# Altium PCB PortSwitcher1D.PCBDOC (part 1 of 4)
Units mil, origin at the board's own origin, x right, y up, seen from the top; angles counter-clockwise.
Board outline 6005.03 x 6005.03 mil, 4 copper layers (Top Layer, InternalPlane1, InternalPlane2, Bottom Layer); 153 components, 325 nets, 1175 pads, 173 vias.
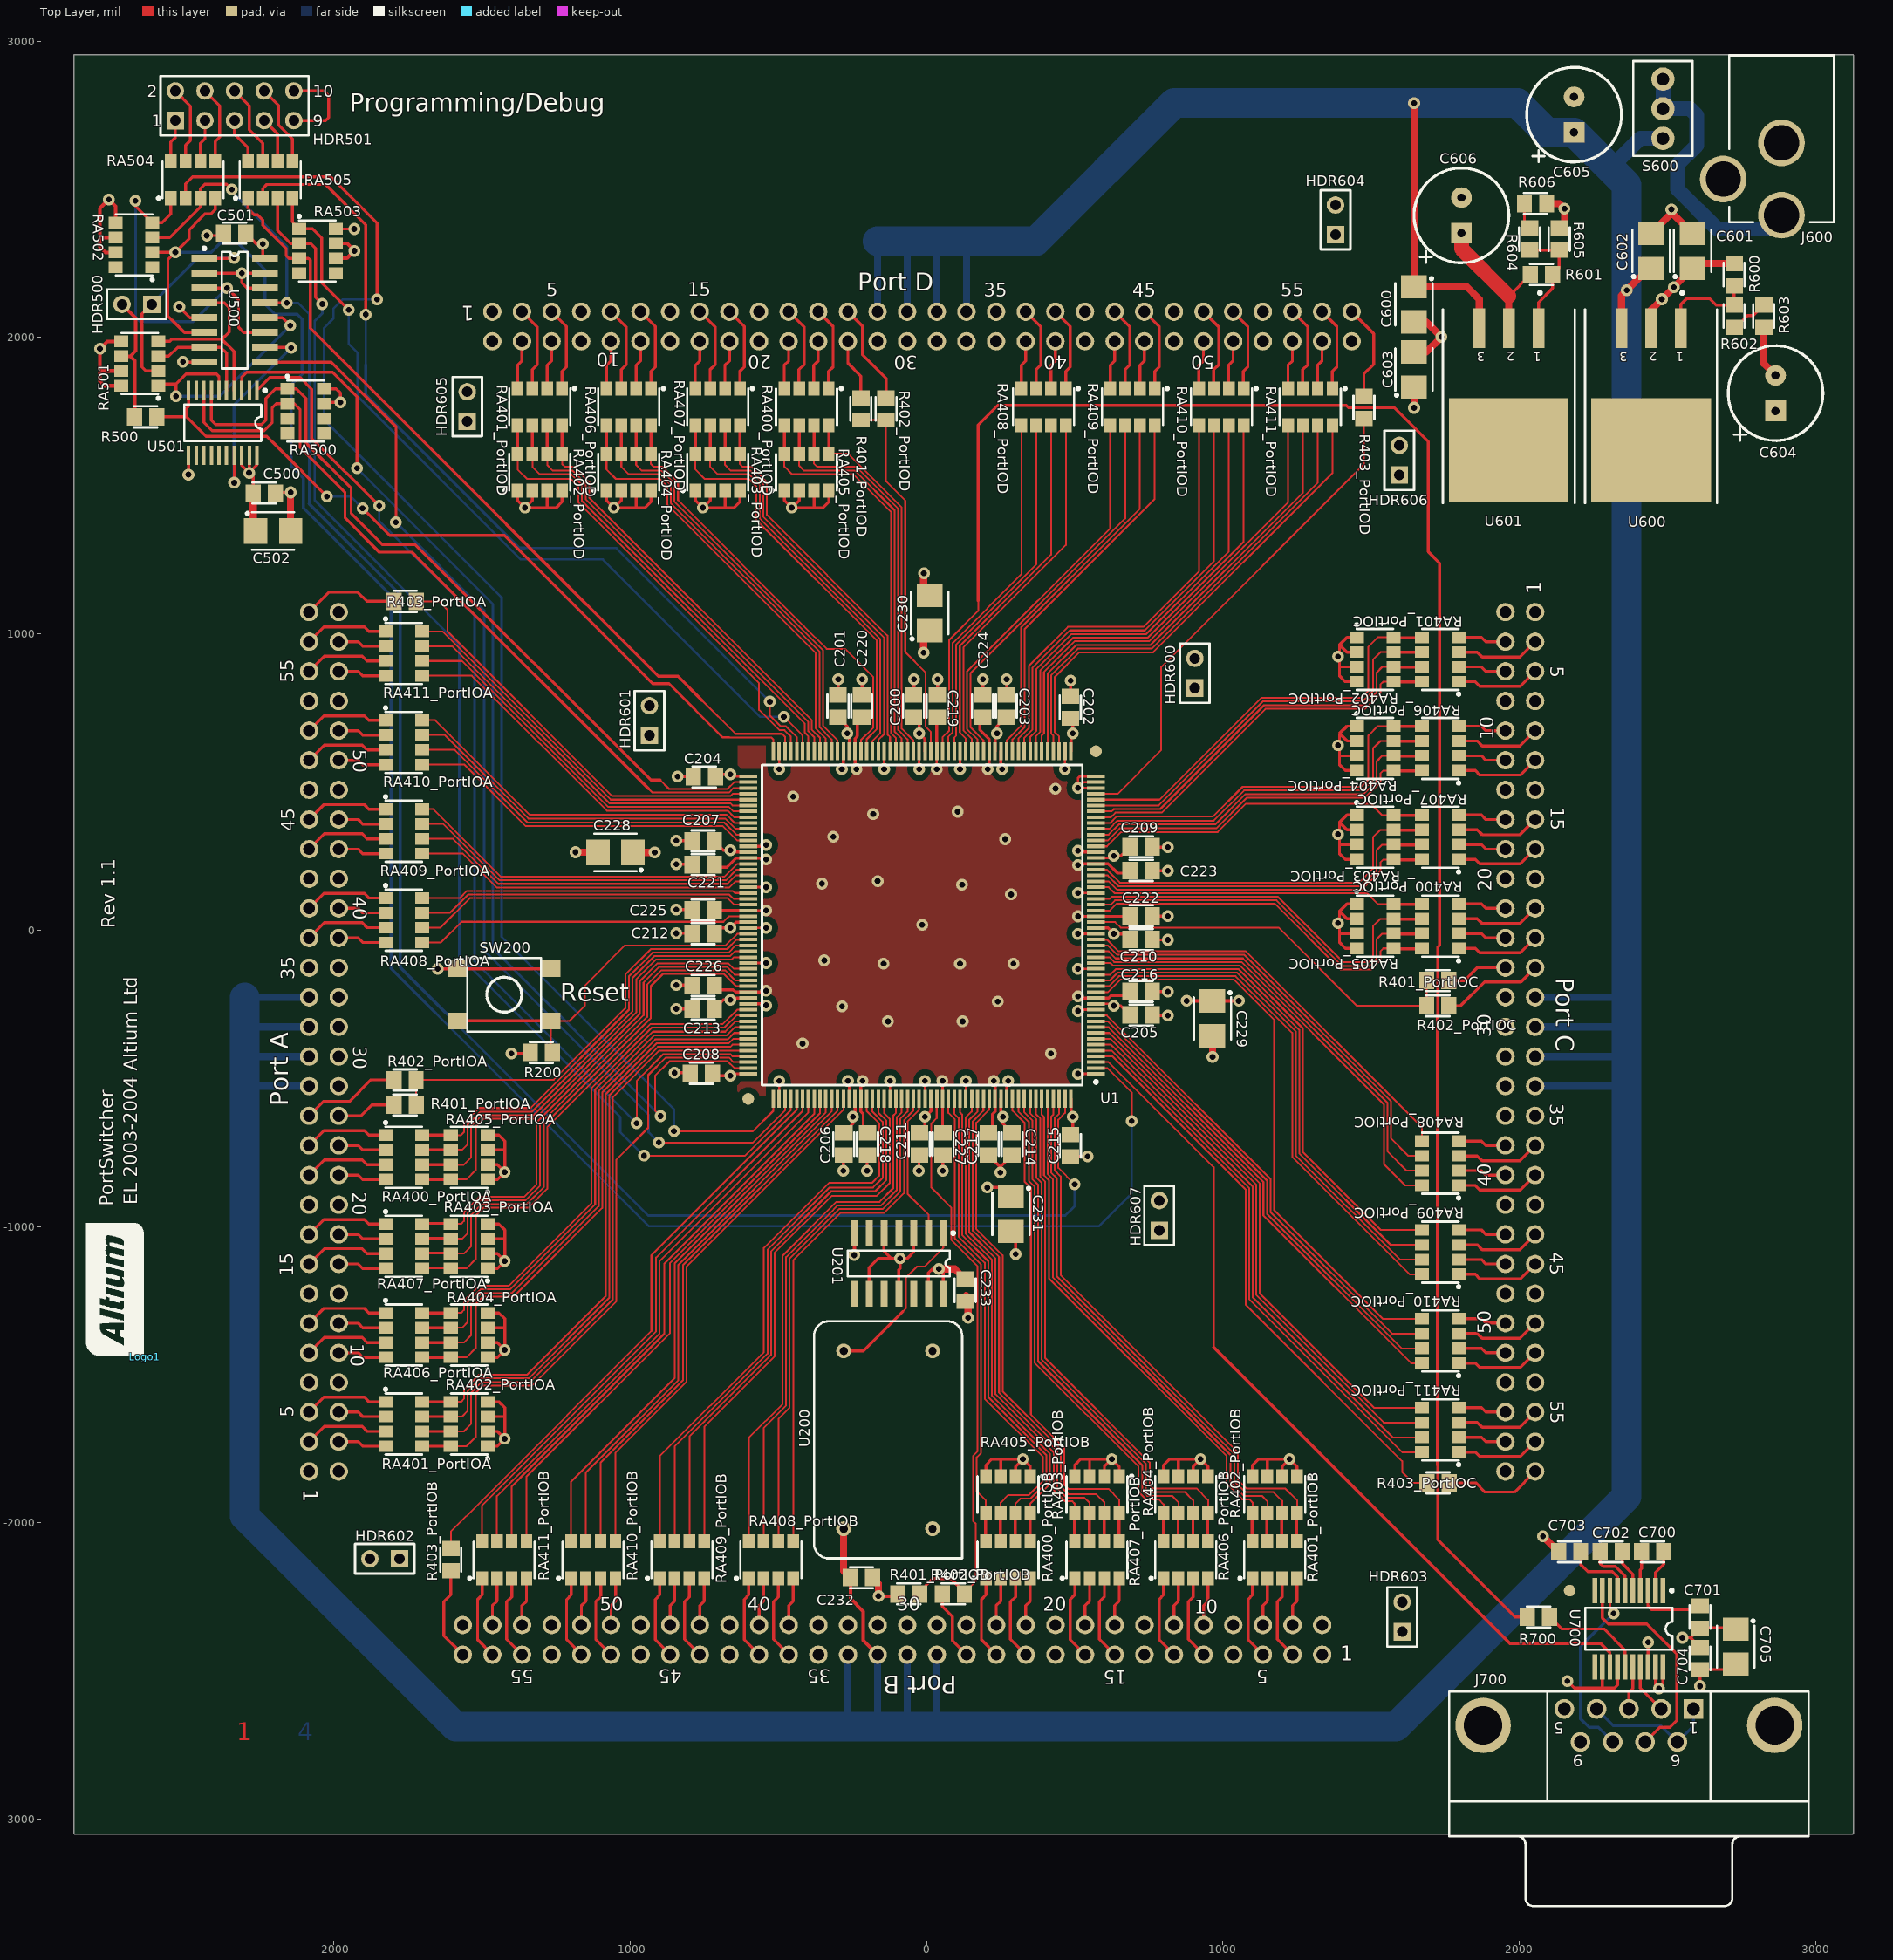
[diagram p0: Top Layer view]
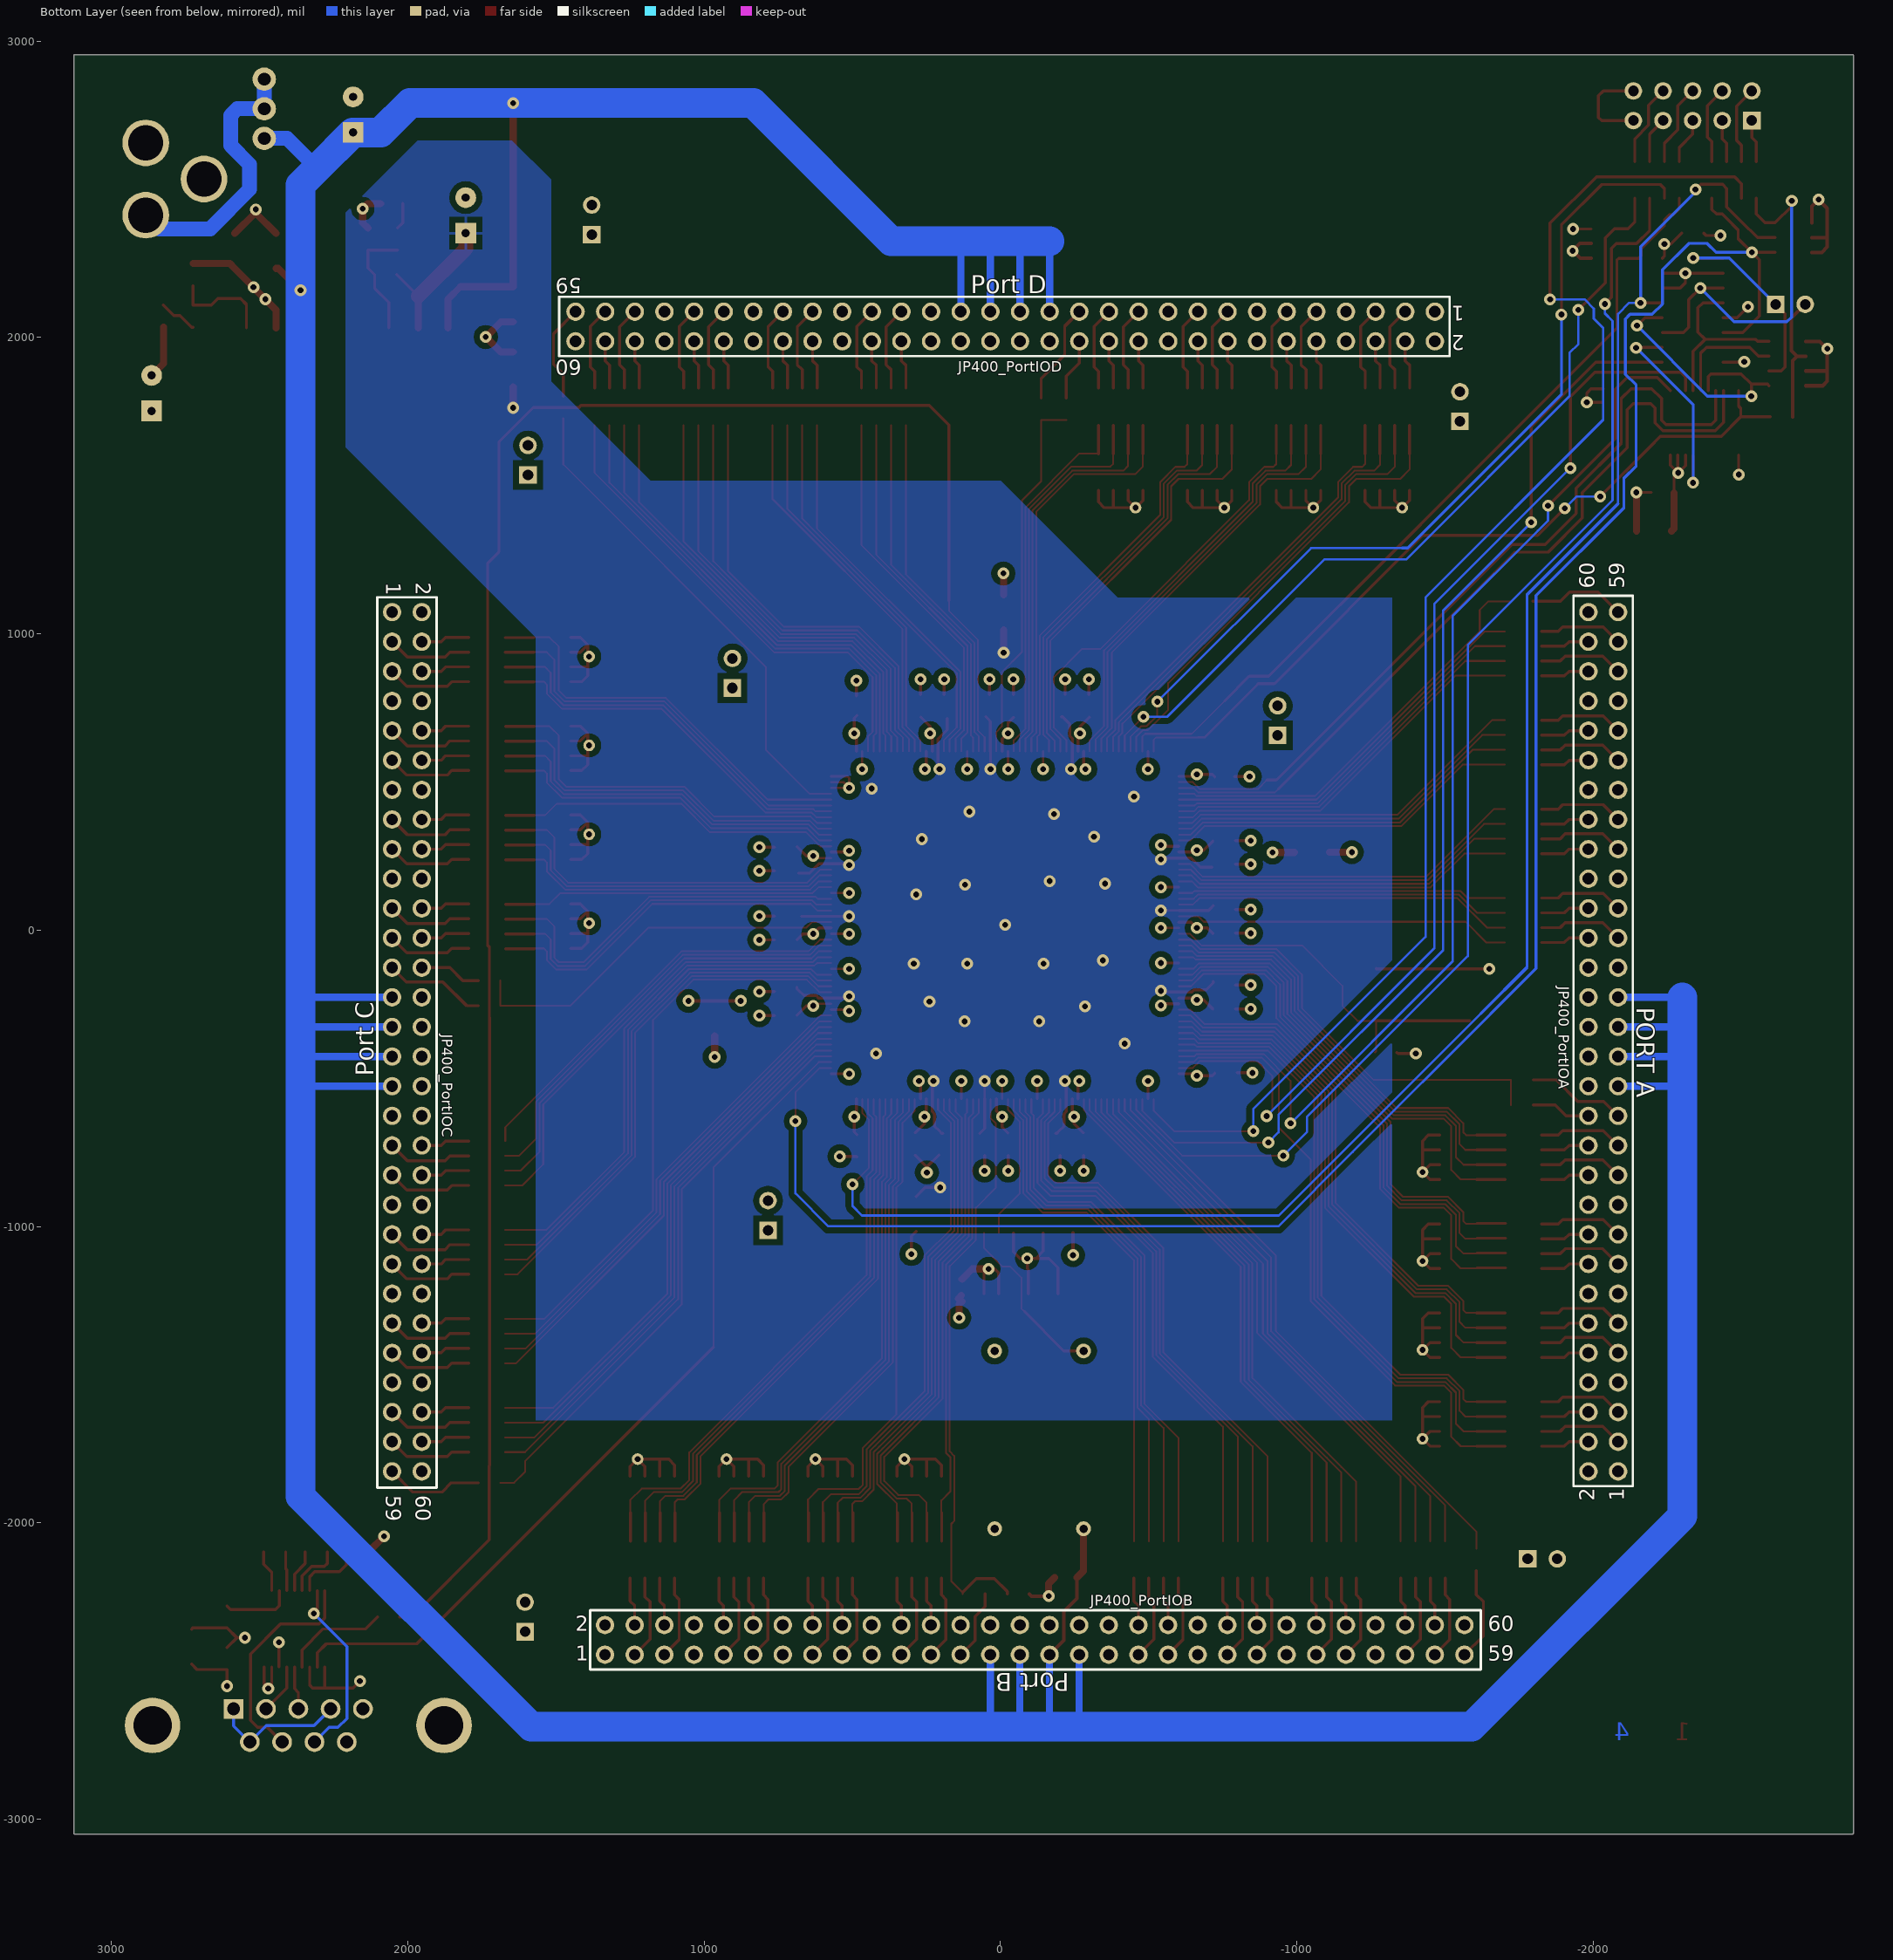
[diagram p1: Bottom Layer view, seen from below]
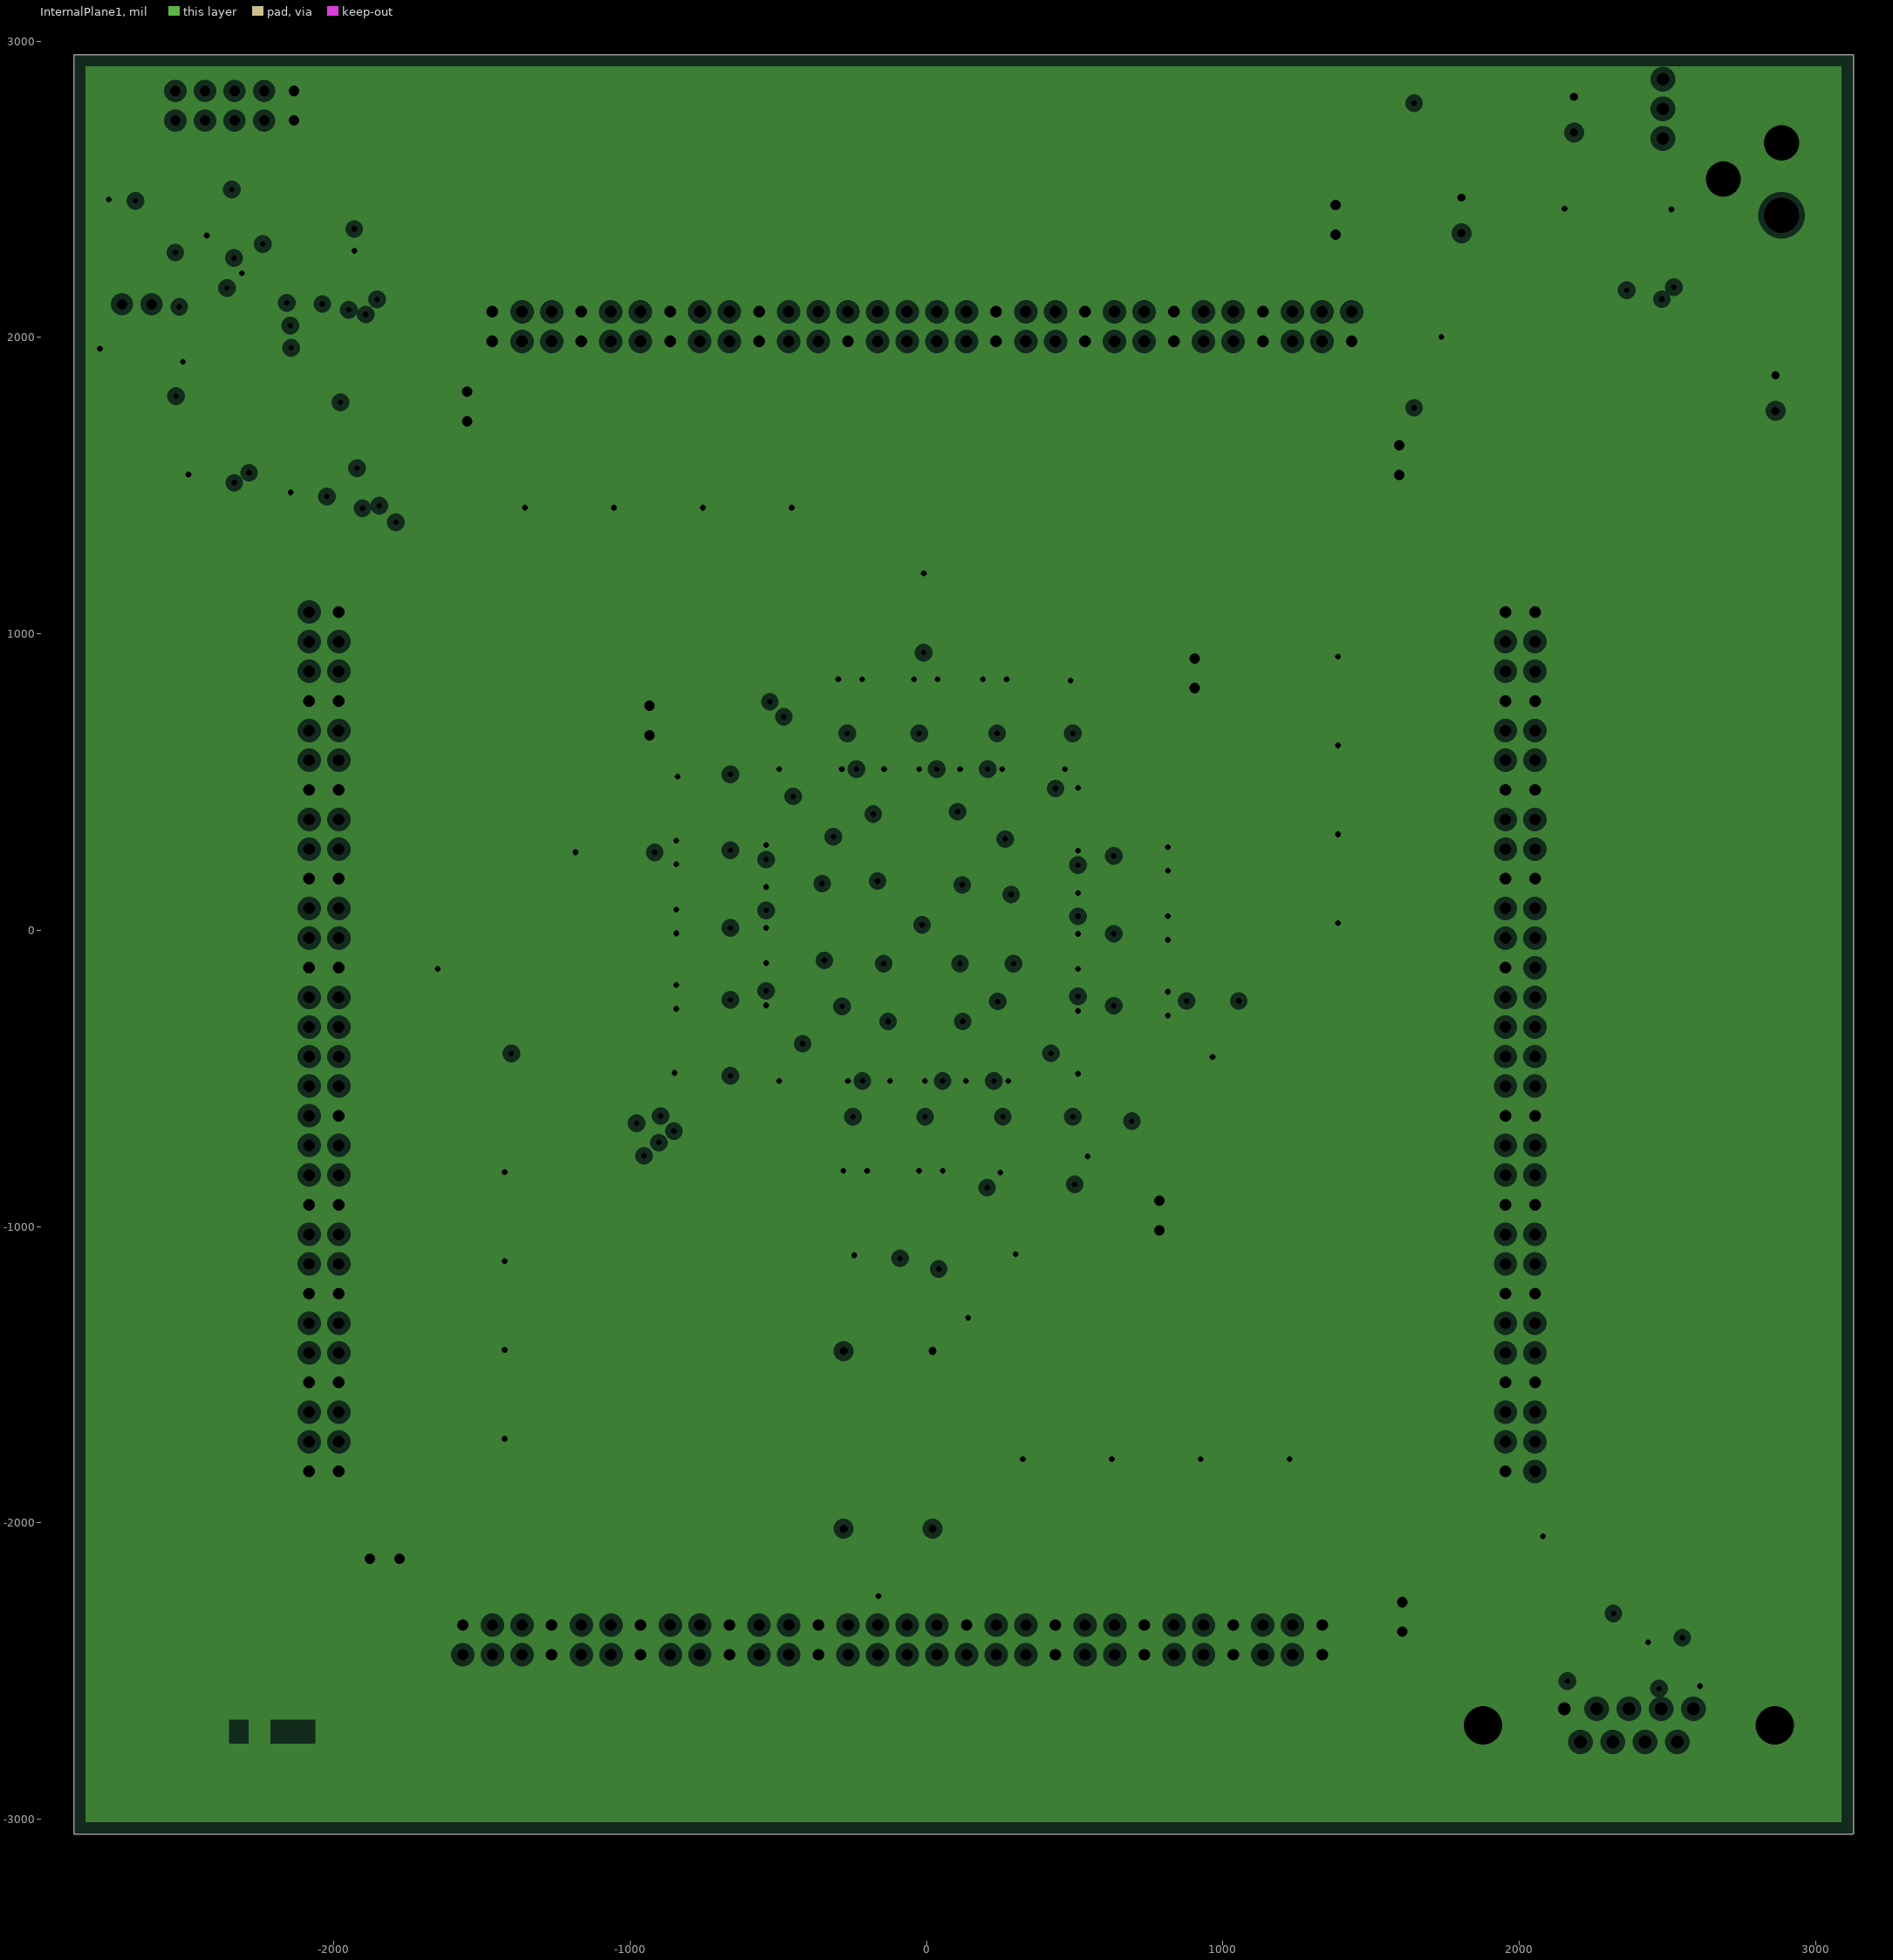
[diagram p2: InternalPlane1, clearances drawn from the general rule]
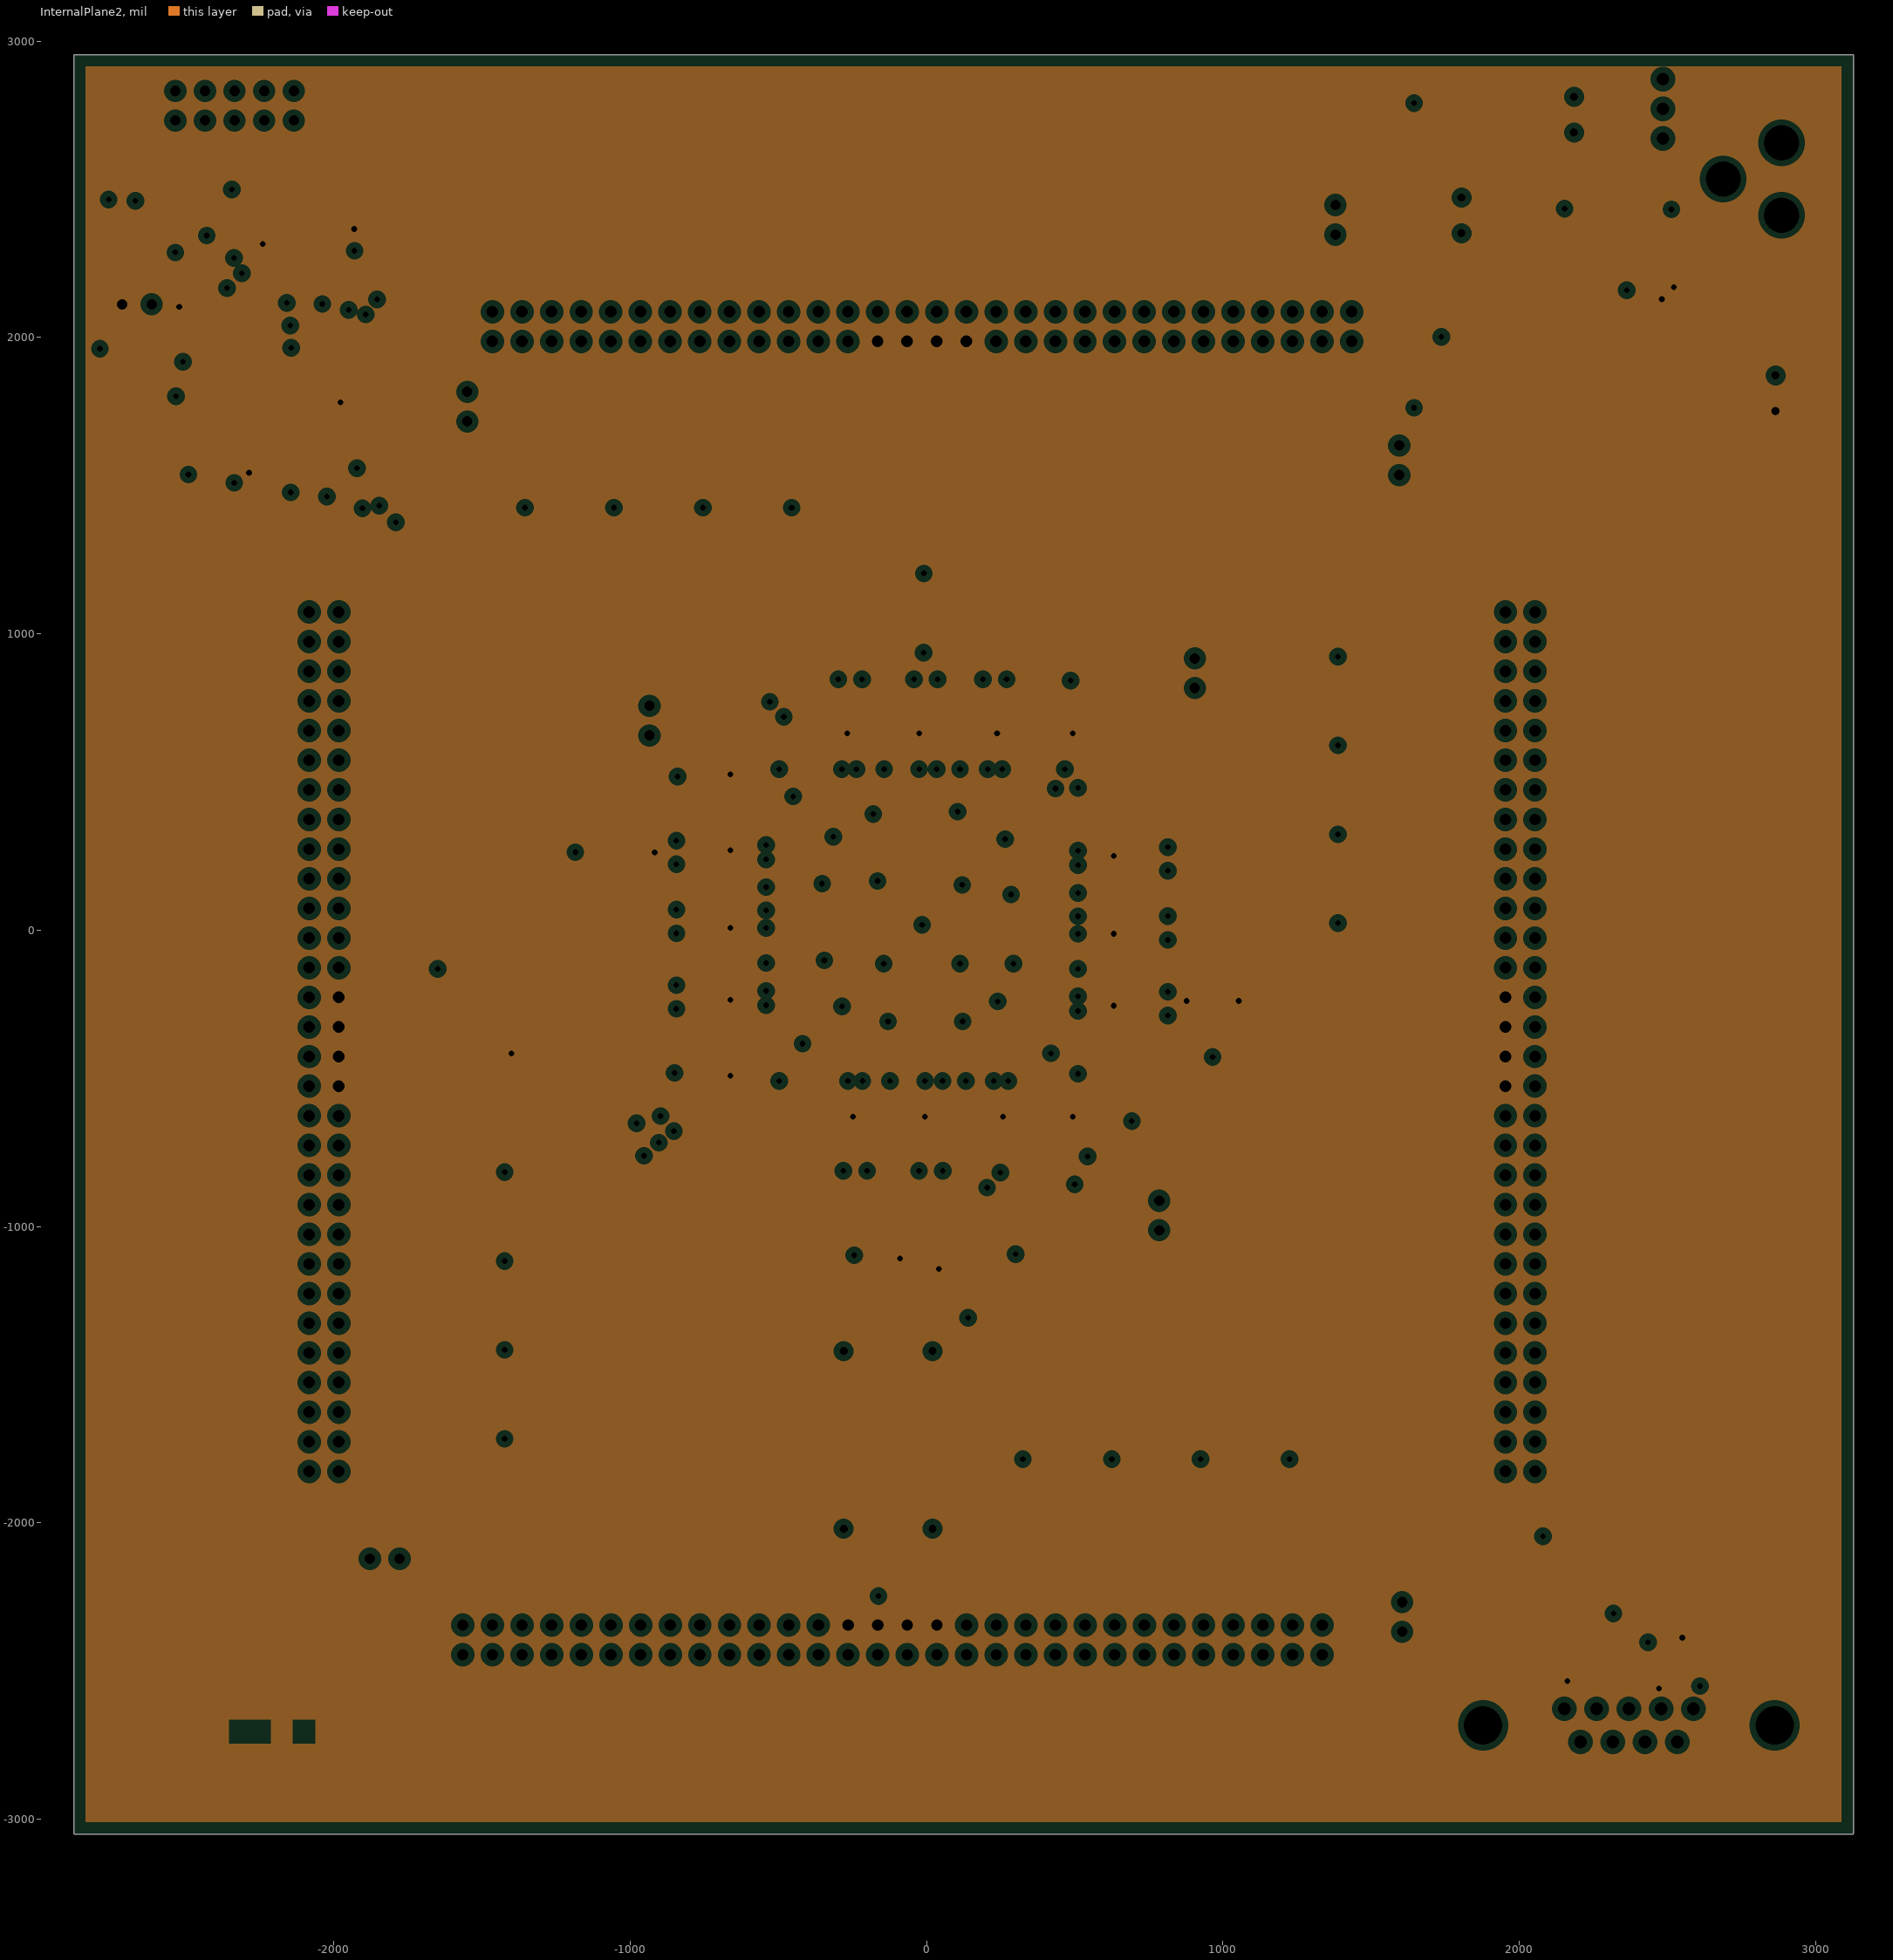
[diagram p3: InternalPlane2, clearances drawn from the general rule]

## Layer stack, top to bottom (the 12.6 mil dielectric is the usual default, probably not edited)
Top Layer: signal copper 1.4
Dielectric: core 12.6, FR-4, Dk 4.8
InternalPlane1: plane copper 1.4, net GND
Dielectric: prepreg 12.6, FR-4, Dk 4.8
InternalPlane2: plane copper 1.4, net VCCO
Dielectric: core 12.6, FR-4, Dk 4.8
Bottom Layer: signal copper 1.4

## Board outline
-2875.26,-3050.22 cw(c-2875.26,-3047.71) -2877.78,-3047.71 -2877.78,2952.29 cw(c-2875.26,2952.29) -2875.26,2954.81 3124.74,2954.81 cw(c3124.74,2952.29) 3127.25,2952.29 3127.25,-3047.71 cw(c3124.74,-3047.71) 3124.74,-3050.22

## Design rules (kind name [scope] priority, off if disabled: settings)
Clearance Clearance_Polygon [InPolygon] p1: gap=20
Clearance Clearance_FPGA_Pins [IsPad and InComponent('U1')] p2: gap=7
Clearance [All] p3: gap=6
ComponentClearance [All] p1: gap=0 collisioncheckmode=3 verticalgap=10 showdistances=FALSE
FabricationTestPointUsage TestPointUsage [All] p1: valid=0 allowmultiple=FALSE
FabricationTestpoint Testpoint [All] p1: side=3 testpointundercomponent=TRUE minsize=40 maxsize=100 preferedsize=60 minholesize=0 maxholesize=40 preferedholesize=32 testpointgrid=1 allowsidetop=TRUE allowsidebottom=TRUE usegrid=TRUE gridtolerance=0.01
FanoutControl Fanout_LCC [IsLCC] p2: bgadir=Out bgaviamode=Centered fanoutstyle=Auto fanoutdirection=InOnly viagrid=1 // Fanout_LCC (Default Rule)
FanoutControl Fanout_SOIC [IsSOIC] p3: bgadir=Out bgaviamode=Centered fanoutstyle=Auto fanoutdirection=OutOnly viagrid=1 // Fanout_SOIC (Default Rule)
FanoutControl Fanout_Small [(CompPinCount < 5)] p4: bgadir=Out bgaviamode=Centered fanoutstyle=Auto fanoutdirection=OutOnly viagrid=1 // Fanout_Small (Default Rule)
FanoutControl Fanout_Default [All] p5: bgadir=Out bgaviamode=Centered fanoutstyle=Auto fanoutdirection=OutThenIn viagrid=1 // Fanout_Default (Default Rule)
HoleSize HoleSize_J600 [Ispad and InComponent('J600')] p1: absolutevalues=TRUE maxlimit=122.05 minlimit=114.17 maxpercent=80.000 minpercent=20.000
HoleSize HoleSize_J700_mounting [Ispad and InComponent('J700') and (Name like 'J700-1?')] p2: absolutevalues=TRUE maxlimit=129.92 minlimit=129.92 maxpercent=80.000 minpercent=20.000
HoleSize [All] p3: absolutevalues=TRUE maxlimit=100 minlimit=1 maxpercent=80.000 minpercent=20.000
PlaneClearance [All] p1: clearance=20
PlaneConnect [All] p1: planeconnectstyle=Relief reliefexpansion=20 reliefentries=4 reliefconductorwidth=10 reliefairgap=10
PolygonConnect [All] p1: connectstyle=Relief reliefconductorwidth=10 reliefentries=4 polygonreliefangle="90 Angle"
RoomDefinition "U_FPGA Sheet1" [InComponentClass('U_FPGA Sheet1')] p1: confinementstyle=ConfineIn formatcopy=TRUE lockcomponents=FALSE outline -965,-985 975,-985 975,955 -965,955
RoomDefinition "U_FPGA Symbol1" [InComponentClass('U_FPGA Symbol1')] p2: confinementstyle=ConfineIn formatcopy=TRUE lockcomponents=FALSE outline -1791.86,-2316.03 1405,-2316.03 1405,1258.54 -1791.86,1258.54
RoomDefinition U_PCB_JTAG1D [InComponentClass('U_PCB_JTAG1D')] p3: confinementstyle=ConfineIn formatcopy=TRUE lockcomponents=FALSE outline -1940,1239.84 -1940,2920 -2775,2920 -2775,1239.84
RoomDefinition PortIOC [InComponentClass('PortIOC')] p4: confinementstyle=ConfineIn formatcopy=FALSE lockcomponents=FALSE outline 1378.5,1241.3 1378.5,-2063.7 2218.5,-2063.7 2218.5,1241.3
RoomDefinition PortIOB [InComponentClass('PortIOB')] p5: confinementstyle=ConfineIn formatcopy=TRUE lockcomponents=FALSE outline 1535,-1772.2 -1770,-1772.2 -1770,-2612.2 1535,-2612.2
RoomDefinition PortIOD [InComponentClass('PortIOD')] p6: confinementstyle=ConfineIn formatcopy=FALSE lockcomponents=FALSE outline -1635,1378.5 1670,1378.5 1670,2218.5 -1635,2218.5
RoomDefinition PCB_Power1D [InComponentClass('PCB_Power1D')] p7: confinementstyle=ConfineIn formatcopy=TRUE lockcomponents=FALSE outline -2850,-3055 3125.18,-3055 3125.18,2970.7 -2850,2970.7
RoomDefinition U_PCB_RS2321D [InComponentClass('U_PCB_RS2321D')] p8: confinementstyle=ConfineIn formatcopy=TRUE lockcomponents=FALSE outline 1660,-3340 3145,-3340 3145,-2000 1660,-2000
RoomDefinition PortIOA [InComponentClass('PortIOA')] p9: confinementstyle=ConfineIn formatcopy=FALSE lockcomponents=FALSE outline -1378.5,-2028.7 -1378.5,1276.3 -2218.5,1276.3 -2218.5,-2028.7
RoutingPriority RoutingPriority_Supply [innet('VCCO') or innet('VCCINT') or innet('5V') or innet('GND')] p1: routingpriority=80
RoutingPriority [All] p2: routingpriority=0
RoutingVias [All] p1: holewidth=19.68 width=40 viastyle="Through Hole" minholewidth=19.68 minwidth=40 maxholewidth=31.5 maxwidth=70
SMDNeckDown [All] p1: percent=60.000
SilkscreenOverComponentPads [All] p1: minsilkscreentomaskgap=10
SolderMaskExpansion [All] p1: expansion=4
Width Width_Power [innet('VCCO') or innet('VCCINT') or innet('5V')] p1: maxlimit=100 minlimit=6 preferedwidth=10
Width [All] p2: maxlimit=50 minlimit=6 preferedwidth=6
16 further rules are at their usual default settings.

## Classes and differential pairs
channel class PCB_PortIO1D: PortIOA PortIOB PortIOC PortIOD
component class PortIOD: JP400_PortIOD R401_PortIOD R402_PortIOD R403_PortIOD RA400_PortIOD RA401_PortIOD RA402_PortIOD RA403_PortIOD RA404_PortIOD RA405_PortIOD RA406_PortIOD RA407_PortIOD RA408_PortIOD RA409_PortIOD RA410_PortIOD RA411_PortIOD
component class PortIOC: JP400_PortIOC R401_PortIOC R402_PortIOC R403_PortIOC RA400_PortIOC RA401_PortIOC RA402_PortIOC RA403_PortIOC RA404_PortIOC RA405_PortIOC RA406_PortIOC RA407_PortIOC RA408_PortIOC RA409_PortIOC RA410_PortIOC RA411_PortIOC
component class PortIOB: JP400_PortIOB R401_PortIOB R402_PortIOB R403_PortIOB RA400_PortIOB RA401_PortIOB RA402_PortIOB RA403_PortIOB RA404_PortIOB RA405_PortIOB RA406_PortIOB RA407_PortIOB RA408_PortIOB RA409_PortIOB RA410_PortIOB RA411_PortIOB
component class PortIOA: JP400_PortIOA R401_PortIOA R402_PortIOA R403_PortIOA RA400_PortIOA RA401_PortIOA RA402_PortIOA RA403_PortIOA RA404_PortIOA RA405_PortIOA RA406_PortIOA RA407_PortIOA RA408_PortIOA RA409_PortIOA RA410_PortIOA RA411_PortIOA
component class PCB_Power1D: C600 C601 C602 C603 C604 C605 C606 HDR600 HDR601 HDR602 HDR603 HDR604 HDR605 HDR606 HDR607 J600 R600 R601 R602 R603 R604 R605 R606 S600 U600 U601
component class "U_FPGA Symbol1": C200 C201 C202 C203 C204 C205 C206 C207 C208 C209 C210 C211 C212 C213 C214 C215 C216 C217 C218 C219 C220 C221 C222 C223 C224 C225 C226 C227 C228 C229 C230 C231 C232 C233 R200 SW200 U200 U201
component class "U_FPGA Sheet1": U1
net class INA[16..0]: INA0 INA1 INA2 INA3 INA4 INA5 INA6 INA7 INA8 INA9 INA10 INA11 INA12 INA13 INA14 INA15 INA16
net class INB[16..0]: INB0 INB1 INB2 INB3 INB4 INB5 INB6 INB7 INB8 INB9 INB10 INB11 INB12 INB13 INB14 INB15 INB16
net class INC[16..0]: INC0 INC1 INC2 INC3 INC4 INC5 INC6 INC7 INC8 INC9 INC10 INC11 INC12 INC13 INC14 INC15 INC16
net class IND[16..0]: IND0 IND1 IND2 IND3 IND4 IND5 IND6 IND7 IND8 IND9 IND10 IND11 IND12 IND13 IND14 IND15 IND16
net class OUTA[16..0]: OUTA0 OUTA1 OUTA2 OUTA3 OUTA4 OUTA5 OUTA6 OUTA7 OUTA8 OUTA9 OUTA10 OUTA11 OUTA12 OUTA13 OUTA14 OUTA15 OUTA16
net class OUTB[16..0]: OUTB0 OUTB1 OUTB2 OUTB3 OUTB4 OUTB5 OUTB6 OUTB7 OUTB8 OUTB9 OUTB10 OUTB11 OUTB12 OUTB13 OUTB14 OUTB15 OUTB16
net class OUTC[16..0]: OUTC0 OUTC1 OUTC2 OUTC3 OUTC4 OUTC5 OUTC6 OUTC7 OUTC8 OUTC9 OUTC10 OUTC11 OUTC12 OUTC13 OUTC14 OUTC15 OUTC16
net class OUTD[16..0]: OUTD0 OUTD1 OUTD2 OUTD3 OUTD4 OUTD5 OUTD6 OUTD7 OUTD8 OUTD9 OUTD10 OUTD11 OUTD12 OUTD13 OUTD14 OUTD15 OUTD16
component class U_PCB_JTAG1D: C500 C501 C502 HDR500 HDR501 R500 RA500 RA501 RA502 RA503 RA504 RA505 U500 U501
component class U_PCB_RS2321D: C700 C701 C702 C703 C704 C705 J700 R700 U700

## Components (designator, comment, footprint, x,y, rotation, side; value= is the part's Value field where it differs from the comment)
C200 "100n" CC2012-0805 -44.26,756.29 r90 top
C201 "100n" CC2012-0805 -299.26,756.29 r90 top
C202 "100n" CC2012-0805 484.74,752.29 r90 top
C203 "100n" CC2012-0805 268.74,756.29 r90 top
C204 "100n" CC2012-0805 -750.26,517.29 r180 top
C205 "100n" CC2012-0805 723.74,-286.39 r0 top
C206 "100n" CC2012-0805 -279.58,-721.71 r270 top
C207 "100n" CC2012-0805 -754.26,301.29 r180 top
C208 "100n" CC2012-0805 -760.26,-482.71 r0 top
C209 "100n" CC2012-0805 723.74,281.61 r180 top
C210 "100n" CC2012-0805 723.74,-31.39 r180 top
C211 "100n" CC2012-0805 -24.58,-721.71 r90 top
C212 "100n" CC2012-0805 -754.26,-11.71 r0 top
C213 "100n" CC2012-0805 -754.26,-266.71 r0 top
C214 "100n" CC2012-0805 288.42,-721.71 r90 top
C215 "100n" CC2012-0805 484.74,-727.71 r90 top
C216 "100n" CC2012-0805 723.74,-206.39 r0 top
C217 "100n" CC2012-0805 208.42,-721.71 r270 top
C218 "100n" CC2012-0805 -199.58,-721.71 r270 top
C219 "100n" CC2012-0805 35.74,756.29 r90 top
C220 "100n" CC2012-0805 -219.26,756.29 r90 top
C221 "100n" CC2012-0805 -754.26,221.29 r180 top
C222 "100n" CC2012-0805 723.74,48.61 r180 top
C223 "100n" CC2012-0805 723.74,201.61 r180 top
C224 "100n" CC2012-0805 188.74,756.29 r270 top
C225 "100n" CC2012-0805 -754.26,68.29 r0 top
C226 "100n" CC2012-0805 -754.26,-186.71 r0 top
C227 "100n" CC2012-0805 55.42,-721.71 r90 top
C228 "10uF" MCCT-B -1050.26,262.29 r180 top
C229 "10uF" MCCT-B 964.74,-297.71 r270 top
C230 "10uF" MCCT-B 10,1070 r90 top
C231 "10uF" MCCT-B 284.74,-957.71 r270 top
C232 "100n" CC2012-0805 -220,-2185 r0 top
C233 "100n" CC2012-0805 130,-1215 r270 top
C500 "100n" CC2012-0805 -2235.26,1475.08 r0 top
C501 "100n" CC2012-0805 -2335.26,2352.29 r180 top
C502 "10uF" MCCT-B -2205.26,1347.29 r0 top
C600 "10uF" MCCT-B 1644.74,2112.29 r270 top
C601 "10uF" MCCT-B 2584.74,2292.29 r90 top
C602 "10uF" MCCT-B 2444.74,2292.29 r90 top
C603 "10uF" MCCT-B 1644.74,1892.29 r90 top
C604 "470uF 16V" RB8/3.5 2864.74,1812.29 r180 top
C605 "470uF 16V" RB8/3.5 2184.74,2752.29 r180 top
C606 "470uF 16V" RB8/3.5 1804.74,2412.29 r180 top
C700 "100n" CC2012-0805 2449.74,-2097.71 r180 top
C701 "100n" CC2012-0805 2609.74,-2317.71 r90 top
C702 "100n" CC2012-0805 2309.74,-2097.71 r180 top
C703 "100n" CC2012-0805 2169.74,-2097.71 r180 top
C704 "100n" CC2012-0805 2609.74,-2457.71 r270 top
C705 "10uF" MCCT-B 2729.74,-2417.71 r270 top
HDR500 "Header 2" HDR1X2 -2615.26,2112.29 r180 top
HDR501 "Header 5X2" HDR2X5 -2535.26,2732.29 r0 top
HDR600 "Header 2" HDR1X2 904.74,817.29 r90 top
HDR601 "Header 2" HDR1X2 -935.26,657.29 r90 top
HDR602 "Header 2" HDR1X2 -1778.77,-2121.41 r180 top
HDR603 "Header 2" HDR1X2 1604.74,-2367.71 r90 top
HDR604 "Header 2" HDR1X2 1379.74,2347.29 r90 top
HDR605 "Header 2" HDR1X2 -1550.26,1717.09 r90 top
HDR606 "Header 2" HDR1X2 1594.74,1535.99 r90 top
HDR607 "Header 2" HDR1X2 784.74,-1012.71 r90 top
J600 "PWR2.5" PWR2.5 2884.74,2952.29 r270 top
J700 "DB9 Female" DSUB1.385-2H9 2369.74,-3057.71 r180 top
JP400_PortIOA "Header 30X2" HDR2X30 -2083.77,-1826.41 r90 bottom (schematic designator JP400)
JP400_PortIOB "Header 30X2" HDR2X30 1334.74,-2444.91 r180 bottom (schematic designator JP400)
JP400_PortIOC "Header 30X2" HDR2X30 2053.24,1073.59 r270 bottom (schematic designator JP400)
JP400_PortIOD "Header 30X2" HDR2X30 -1465.66,2087.37 r0 bottom (schematic designator JP400)
Logo1 "Comment" AltiumLogo48mm -2638.02,-1440.66 r90 top
R200 "4K7" CC2012-0805 -1300.26,-412.71 r180 top
R401_PortIOA "100k" CC2012-0805 -1760,-590 r0 top (schematic designator R401)
R401_PortIOB "100k" CC2012-0805 -60,-2240 r0 top (schematic designator R401)
R401_PortIOC "100k" CC2012-0805 1725,-170 r180 top (schematic designator R401)
R401_PortIOD "100k" CC2012-0805 -222.07,1759.13 r270 top (schematic designator R401)
R402_PortIOA "100R" CC2012-0805 -1760,-505 r180 top (schematic designator R402)
R402_PortIOB "100R" CC2012-0805 90,-2240 r180 top (schematic designator R402)
R402_PortIOC "100R" CC2012-0805 1725,-255 r0 top (schematic designator R402)
R402_PortIOD "100R" CC2012-0805 -137.07,1759.13 r90 top (schematic designator R402)
R403_PortIOA "100R" CC2012-0805 -1759.55,1109.68 r180 top (schematic designator R403)
R403_PortIOB "100R" CC2012-0805 -1605.5,-2124.5 r270 top (schematic designator R403)
R403_PortIOC "100R" CC2012-0805 1725.43,-1865 r0 top (schematic designator R403)
R403_PortIOD "100R" CC2012-0805 1475.5,1764.5 r90 top (schematic designator R403)
R500 "330R" CC2012-0805 -2635.26,1732.29 r0 top
R600 "120R" CC2012-0805 2724.74,2212.29 r90 top
R601 "120R" CC2012-0805 2074.74,2212.29 r180 top
R602 "100R" CC2012-0805 2724.74,2072.29 r90 top
R603 "100R" CC2012-0805 2824.74,2072.29 r90 top
R604 "47R" CC2012-0805 2034.74,2332.29 r270 top
R605 "nf(47R)" CC2012-0805 2134.74,2332.29 r270 top
R606 "5R6" CC2012-0805 2054.74,2452.29 r180 top
R700 "100R" CC2012-0805 2064.74,-2317.71 r180 top
RA400_PortIOA "100R" MNR34 -1763.77,-766.41 r0 top (schematic designator RA400)
RA400_PortIOB "100R" MNR34 274.74,-2124.91 r90 top (schematic designator RA400)
RA400_PortIOC "100R" MNR34 1733.24,13.59 r180 top (schematic designator RA400)
RA400_PortIOD "100R" MNR34 -405.26,1765.8 r270 top (schematic designator RA400)
RA401_PortIOA "100R" MNR34 -1763.77,-1666.41 r0 top (schematic designator RA401)
RA401_PortIOB "100R" MNR34 1174.74,-2124.91 r90 top (schematic designator RA401)
RA401_PortIOC "100R" MNR34 1733.24,913.59 r180 top (schematic designator RA401)
RA401_PortIOD "100R" MNR34 -1305.26,1765.8 r270 top (schematic designator RA401)
RA402_PortIOA "100k" MNR34 -1543.77,-1666.41 r180 top (schematic designator RA402)
RA402_PortIOB "100k" MNR34 1174.74,-1904.91 r270 top (schematic designator RA402)
RA402_PortIOC "100k" MNR34 1513.24,913.59 r0 top (schematic designator RA402)
RA402_PortIOD "100k" MNR34 -1305.26,1545.8 r90 top (schematic designator RA402)
RA403_PortIOA "100k" MNR34 -1543.77,-1066.41 r180 top (schematic designator RA403)
RA403_PortIOB "100k" MNR34 574.74,-1904.91 r270 top (schematic designator RA403)
RA403_PortIOC "100k" MNR34 1513.24,313.59 r0 top (schematic designator RA403)
RA403_PortIOD "100k" MNR34 -705.26,1545.8 r90 top (schematic designator RA403)
RA404_PortIOA "100k" MNR34 -1543.77,-1366.41 r180 top (schematic designator RA404)
RA404_PortIOB "100k" MNR34 874.74,-1904.91 r270 top (schematic designator RA404)
RA404_PortIOC "100k" MNR34 1513.24,613.59 r0 top (schematic designator RA404)
RA404_PortIOD "100k" MNR34 -1005.26,1545.8 r90 top (schematic designator RA404)
RA405_PortIOA "100k" MNR34 -1543.77,-766.41 r180 top (schematic designator RA405)
RA405_PortIOB "100k" MNR34 274.74,-1904.91 r270 top (schematic designator RA405)
RA405_PortIOC "100k" MNR34 1513.24,13.59 r0 top (schematic designator RA405)
RA405_PortIOD "100k" MNR34 -405.26,1545.8 r90 top (schematic designator RA405)
RA406_PortIOA "100R" MNR34 -1763.77,-1366.41 r0 top (schematic designator RA406)
RA406_PortIOB "100R" MNR34 874.74,-2124.91 r90 top (schematic designator RA406)
RA406_PortIOC "100R" MNR34 1733.24,613.59 r180 top (schematic designator RA406)
RA406_PortIOD "100R" MNR34 -1005.26,1765.8 r270 top (schematic designator RA406)
RA407_PortIOA "100R" MNR34 -1763.77,-1066.41 r0 top (schematic designator RA407)
RA407_PortIOB "100R" MNR34 574.74,-2124.91 r90 top (schematic designator RA407)
RA407_PortIOC "100R" MNR34 1733.24,313.59 r180 top (schematic designator RA407)
RA407_PortIOD "100R" MNR34 -705.26,1765.8 r270 top (schematic designator RA407)
RA408_PortIOA "100R" MNR34 -1763.77,33.59 r0 top (schematic designator RA408)
RA408_PortIOB "100R" MNR34 -525.26,-2124.91 r90 top (schematic designator RA408)
RA408_PortIOC "100R" MNR34 1733.24,-786.41 r180 top (schematic designator RA408)
RA408_PortIOD "100R" MNR34 394.74,1765.8 r270 top (schematic designator RA408)
RA409_PortIOA "100R" MNR34 -1763.77,333.59 r0 top (schematic designator RA409)
RA409_PortIOB "100R" MNR34 -825.26,-2124.91 r90 top (schematic designator RA409)
RA409_PortIOC "100R" MNR34 1733.24,-1086.41 r180 top (schematic designator RA409)
RA409_PortIOD "100R" MNR34 694.74,1765.8 r270 top (schematic designator RA409)
RA410_PortIOA "100R" MNR34 -1763.77,633.59 r0 top (schematic designator RA410)
RA410_PortIOB "100R" MNR34 -1125.26,-2124.91 r90 top (schematic designator RA410)
RA410_PortIOC "100R" MNR34 1733.24,-1386.41 r180 top (schematic designator RA410)
RA410_PortIOD "100R" MNR34 994.74,1765.8 r270 top (schematic designator RA410)
RA411_PortIOA "100R" MNR34 -1763.77,933.59 r0 top (schematic designator RA411)
RA411_PortIOB "100R" MNR34 -1425.26,-2124.91 r90 top (schematic designator RA411)
RA411_PortIOC "100R" MNR34 1733.24,-1686.41 r180 top (schematic designator RA411)
RA411_PortIOD "100R" MNR34 1294.74,1765.8 r270 top (schematic designator RA411)
RA500 "3k3" MNR34 -2095.26,1752.29 r0 top
RA501 "4k7" MNR34 -2655.26,1912.29 r180 top
RA502 "4k7" MNR34 -2675.26,2312.29 r180 top
RA503 "4k7" MNR34 -2055.26,2292.29 r0 top
RA504 "100R" MNR34 -2475.26,2532.29 r90 top
RA505 "100R" MNR34 -2215.26,2532.29 r90 top
S600 "SPST" PCB_SWITCH 2484.74,2672.29 r180 top
SW200 "B3FS" B3FS_SWITCH -1425.26,-217.71 r0 top
U1 "XC2S300E-6PQ208C" PQ208 -15.26,17.29 r180 top
U200 "32MHz" XO600CP 20,-2020 r90 top
U201 "MC74LVX04D" 751A-03 -94,-1124.44 r180 top
U500 "MC74LCX157D" 751B-05 -2335.26,2092.29 r270 top
U501 "XCF04SVO20C" VO20 -2375.26,1712.29 r180 top
U600 "LM1084IS-ADJ" TO-263 2544.74,2032.29 r180 top
U601 "LM1084IS-ADJ" TO-263 2064.74,2032.29 r180 top
U700 "ICL3225ECA" SSO-G20/P.65 2369.74,-2357.71 r180 top

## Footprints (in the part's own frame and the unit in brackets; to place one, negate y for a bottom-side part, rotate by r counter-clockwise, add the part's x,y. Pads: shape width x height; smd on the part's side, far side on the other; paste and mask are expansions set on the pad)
751A-03 [mm] "Small Outline; 14 Leads; Body Width 3.9 mm; Pitch 1.27 mm"
  rect 0.6x2.2 smd: 1(-3.81,-2.6) 2(-2.54,-2.6) 3(-1.27,-2.6) 4(0,-2.6) 5(1.27,-2.6) 6(2.54,-2.6) 7(3.81,-2.6) 8(3.81,2.6) 9(2.54,2.6) 10(1.27,2.6) 11(0,2.6) 12(-1.27,2.6) 13(-2.54,2.6) 14(-3.81,2.6)
  silkscreen extent -4.78,-2.72 4.38,1.1
751B-05 [mm] "Small Outline; 16 Leads; Body Width 3.9 mm; Pitch 1.27 mm"
  rect 0.6x2.2 smd: 1(-4.445,-2.6) 2(-3.175,-2.6) 3(-1.905,-2.6) 4(-0.635,-2.6) 5(0.635,-2.6) 6(1.905,-2.6) 7(3.175,-2.6) 8(4.445,-2.6) 9(4.445,2.6) 10(3.175,2.6) 11(1.905,2.6) 12(0.635,2.6) 13(-0.635,2.6) 14(-1.905,2.6) 15(-3.175,2.6) 16(-4.445,2.6)
  silkscreen extent -5.42,-2.72 5,1.1
AltiumLogo48mm [mil]
  silkscreen extent 4,4 452,196
B3FS_SWITCH [mm]
  rect 1.6x1.4 smd: 1(4.01,-2.25) 2(-4,-2.25) 3(4.01,2.24) 4(-4,2.24)
  silkscreen extent -3.16,-3.16 3.15,3.15
CC2012-0805 [mm]
  rect 1.3x1.5 smd: 1(-0.95,0) 2(0.95,0)
  silkscreen extent -1,-0.9 1,0.9
DSUB1.385-2H9 [mm]
  rect 1.69x1.69 hole 1.1: 1(-5.54,-10.92)
  round 1.69 hole 1.1: 2(-2.77,-10.92) 3(0,-10.92) 4(2.77,-10.92) 5(5.54,-10.92) 6(-4.155,-8.08) 7(-1.385,-8.08) 8(1.385,-8.08) 9(4.155,-8.08)
  round 4.76 hole 3.3: 10(-12.495,-9.5) 11(12.495,-9.5)
  silkscreen extent -15.4,-12.4 15.4,6
HDR1X2 [mm]
  rect 1.5x1.5 hole 0.9: 1(0,0)
  round 1.5 hole 0.9: 2(2.54,0)
  silkscreen extent -1.27,-1.27 3.81,1.27
HDR2X5 [mm]
  rect 1.5x1.5 hole 0.9: 1(0,0)
  round 1.5 hole 0.9: 2(0,2.54) 3(2.54,0) 4(2.54,2.54) 5(5.08,0) 6(5.08,2.54) 7(7.62,0) 8(7.62,2.54) 9(10.16,0) 10(10.16,2.54)
  silkscreen extent -1.27,-1.27 11.43,3.81
HDR2X30 [mil]
  round 62 hole 39.37: 1(0,0) 2(0,100) 3(100,0) 4(100,100) 5(200,0) 6(200,100) 7(300,0) 8(300,100) 9(400,0) 10(400,100) 11(500,0) 12(500,100) 13(600,0) 14(600,100) 15(700,0) 16(700,100) 17(800,0) 18(800,100) 19(900,0) 20(900,100) 21(1000,0) 22(1000,100) 23(1100,0) 24(1100,100) 25(1200,0) 26(1200,100) 27(1300,0) 28(1300,100) 29(1400,0) 30(1400,100) 31(1500,0) 32(1500,100) 33(1600,0) 34(1600,100) 35(1700,0) 36(1700,100) 37(1800,0) 38(1800,100) 39(1900,0) 40(1900,100) 41(2000,0) 42(2000,100) 43(2100,0) 44(2100,100) 45(2200,0) 46(2200,100) 47(2300,0) 48(2300,100) 49(2400,0) 50(2400,100) 51(2500,0) 52(2500,100) 53(2600,0) 54(2600,100) 55(2700,0) 56(2700,100) 57(2800,0) 58(2800,100) 59(2900,0) 60(2900,100)
  silkscreen extent -50,-50 2955,150
MCCT-B [mm]
  rect 2x2.2 smd: 1(-1.5,0) 2(1.5,0)
  silkscreen extent -2.3,-1.6 1.8,1.6
MNR34 [mm]
  rect 1.2x1 smd: 1(-1.575,1.905) 2(-1.575,0.635) 3(-1.575,-0.635) 4(-1.575,-1.905) 5(1.575,-1.905) 6(1.575,-0.635) 7(1.575,0.635) 8(1.575,1.905)
  silkscreen extent -1.67,-2.62 1.55,3.07
PCB_SWITCH [mm]
  round 2 hole 1.1: 1(0,-5.08) 2(0,-2.54) 3(0,0)
  silkscreen extent -2.54,-6.63 2.54,1.5
PQ208 [mm] "208-Pin Plastic Quad Flat Pack (PQ208)"
  rect 1.55x0.3 smd: 1(-14.9,12.75) 2(-14.9,12.25) 3(-14.9,11.75) 4(-14.9,11.25) 5(-14.9,10.75) 6(-14.9,10.25) 7(-14.9,9.75) 8(-14.9,9.25) 9(-14.9,8.75) 10(-14.9,8.25) 11(-14.9,7.75) 12(-14.9,7.25) 13(-14.9,6.75) 14(-14.9,6.25) 15(-14.9,5.75) 16(-14.9,5.25) 17(-14.9,4.75) 18(-14.9,4.25) 19(-14.9,3.75) 20(-14.9,3.25) 21(-14.9,2.75) 22(-14.9,2.25) 23(-14.9,1.75) 24(-14.9,1.25) 25(-14.9,0.75) 26(-14.9,0.25) 27(-14.9,-0.25) 28(-14.9,-0.75) 29(-14.9,-1.25) 30(-14.9,-1.75) 31(-14.9,-2.25) 32(-14.9,-2.75) 33(-14.9,-3.25) 34(-14.9,-3.75) 35(-14.9,-4.25) 36(-14.9,-4.75) 37(-14.9,-5.25) 38(-14.9,-5.75) 39(-14.9,-6.25) 40(-14.9,-6.75) 41(-14.9,-7.25) 42(-14.9,-7.75) 43(-14.9,-8.25) 44(-14.9,-8.75) 45(-14.9,-9.25) 46(-14.9,-9.75) 47(-14.9,-10.25) 48(-14.9,-10.75) 49(-14.9,-11.25) 50(-14.9,-11.75) 51(-14.9,-12.25) 52(-14.9,-12.75) 105(14.9,-12.75) 106(14.9,-12.25) 107(14.9,-11.75) 108(14.9,-11.25) 109(14.9,-10.75) 110(14.9,-10.25) 111(14.9,-9.75) 112(14.9,-9.25) 113(14.9,-8.75) 114(14.9,-8.25) 115(14.9,-7.75) 116(14.9,-7.25) 117(14.9,-6.75) 118(14.9,-6.25) 119(14.9,-5.75) 120(14.9,-5.25) 121(14.9,-4.75) 122(14.9,-4.25) 123(14.9,-3.75) 124(14.9,-3.25) 125(14.9,-2.75) 126(14.9,-2.25) 127(14.9,-1.75) 128(14.9,-1.25) 129(14.9,-0.75) 130(14.9,-0.25) 131(14.9,0.25) 132(14.9,0.75) 133(14.9,1.25) 134(14.9,1.75) 135(14.9,2.25) 136(14.9,2.75) 137(14.9,3.25) 138(14.9,3.75) 139(14.9,4.25) 140(14.9,4.75) 141(14.9,5.25) 142(14.9,5.75) 143(14.9,6.25) 144(14.9,6.75) 145(14.9,7.25) 146(14.9,7.75) 147(14.9,8.25) 148(14.9,8.75) 149(14.9,9.25) 150(14.9,9.75) 151(14.9,10.25) 152(14.9,10.75) 153(14.9,11.25) 154(14.9,11.75) 155(14.9,12.25) 156(14.9,12.75)
  rect 0.3x1.55 smd: 53(-12.75,-14.9) 54(-12.25,-14.9) 55(-11.75,-14.9) 56(-11.25,-14.9) 57(-10.75,-14.9) 58(-10.25,-14.9) 59(-9.75,-14.9) 60(-9.25,-14.9) 61(-8.75,-14.9) 62(-8.25,-14.9) 63(-7.75,-14.9) 64(-7.25,-14.9) 65(-6.75,-14.9) 66(-6.25,-14.9) 67(-5.75,-14.9) 68(-5.25,-14.9) 69(-4.75,-14.9) 70(-4.25,-14.9) 71(-3.75,-14.9) 72(-3.25,-14.9) 73(-2.75,-14.9) 74(-2.25,-14.9) 75(-1.75,-14.9) 76(-1.25,-14.9) 77(-0.75,-14.9) 78(-0.25,-14.9) 79(0.25,-14.9) 80(0.75,-14.9) 81(1.25,-14.9) 82(1.75,-14.9) 83(2.25,-14.9) 84(2.75,-14.9) 85(3.25,-14.9) 86(3.75,-14.9) 87(4.25,-14.9) 88(4.75,-14.9) 89(5.25,-14.9) 90(5.75,-14.9) 91(6.25,-14.9) 92(6.75,-14.9) 93(7.25,-14.9) 94(7.75,-14.9) 95(8.25,-14.9) 96(8.75,-14.9) 97(9.25,-14.9) 98(9.75,-14.9) 99(10.25,-14.9) 100(10.75,-14.9) 101(11.25,-14.9) 102(11.75,-14.9) 103(12.25,-14.9) 104(12.75,-14.9) 157(12.75,14.9) 158(12.25,14.9) 159(11.75,14.9) 160(11.25,14.9) 161(10.75,14.9) 162(10.25,14.9) 163(9.75,14.9) 164(9.25,14.9) 165(8.75,14.9) 166(8.25,14.9) 167(7.75,14.9) 168(7.25,14.9) 169(6.75,14.9) 170(6.25,14.9) 171(5.75,14.9) 172(5.25,14.9) 173(4.75,14.9) 174(4.25,14.9) 175(3.75,14.9) 176(3.25,14.9) 177(2.75,14.9) 178(2.25,14.9) 179(1.75,14.9) 180(1.25,14.9) 181(0.75,14.9) 182(0.25,14.9) 183(-0.25,14.9) 184(-0.75,14.9) 185(-1.25,14.9) 186(-1.75,14.9) 187(-2.25,14.9) 188(-2.75,14.9) 189(-3.25,14.9) 190(-3.75,14.9) 191(-4.25,14.9) 192(-4.75,14.9) 193(-5.25,14.9) 194(-5.75,14.9) 195(-6.25,14.9) 196(-6.75,14.9) 197(-7.25,14.9) 198(-7.75,14.9) 199(-8.25,14.9) 200(-8.75,14.9) 201(-9.25,14.9) 202(-9.75,14.9) 203(-10.25,14.9) 204(-10.75,14.9) 205(-11.25,14.9) 206(-11.75,14.9) 207(-12.25,14.9) 208(-12.75,14.9)
  silkscreen extent -15.03,-13.72 13.72,13.72
PWR2.5 [mm]
  round 4 hole 3: 1(13.7,0) 2(10.6,-5) 3(7.5,0)
  silkscreen extent 0,-4.48 14.3,4.5
RB8/3.5 [mil]
  rect 70x70 hole 27.56: 1(0,60)
  round 70 hole 27.56: 2(0,-60)
  silkscreen extent -160,-160 160,160
SSO-G20/P.65 [mm]
  rect 0.4x2.15 smd: 1(-2.925,-3.275) 2(-2.275,-3.275) 3(-1.625,-3.275) 4(-0.975,-3.275) 5(-0.325,-3.275) 6(0.325,-3.275) 7(0.975,-3.275) 8(1.625,-3.275) 9(2.275,-3.275) 10(2.925,-3.275) 11(2.925,3.275) 12(2.275,3.275) 13(1.625,3.275) 14(0.975,3.275) 15(0.325,3.275) 16(-0.325,3.275) 17(-0.975,3.275) 18(-1.625,3.275) 19(-2.275,3.275) 20(-2.925,3.275)
  silkscreen extent -3.8,-3.4 3.75,1.8
TO-263 [mm]
  rect 1x3.4 smd: 1(0,0) 2(2.54,0) 3(5.08,0)
  rect 10.25x8.9 smd: 4(2.54,10.45)
  silkscreen extent -3.1,-3.12 8.2,15
VO20 [mm]
  rect 0.3x1.65 smd: 1(-2.925,-2.775) 2(-2.275,-2.775) 3(-1.625,-2.775) 4(-0.975,-2.775) 5(-0.325,-2.775) 6(0.325,-2.775) 7(0.975,-2.775) 8(1.625,-2.775) 9(2.275,-2.775) 10(2.925,-2.775) 11(2.925,2.775) 12(2.275,2.775) 13(1.625,2.775) 14(0.975,2.775) 15(0.325,2.775) 16(-0.325,2.775) 17(-0.975,2.775) 18(-1.625,2.775) 19(-2.275,2.775) 20(-2.925,2.775)
  silkscreen extent -3.75,-2.9 3.3,1.55
XO600CP [mm]
  round 1.27 hole 0.7: 1(0,0) 7(15.24,0) 8(15.24,7.62) 14(0,7.62)
  silkscreen extent -2.54,-2.54 17.78,10.16

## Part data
C200 C201 C202 C203 C204 C205 C206 C207 C208 C209 C210 C211 C212 C213 C214 C215 C216 C217 C218 C219 C220 C221 C222 C223 C224 C225 C226 C227 C232 C233 C500 C501 C700 C701 C702 C703 C704: library part CAP, "Capacitor"
C228 C229 C230 C231 C502 C600 C601 C602 C603 C604 C605 C606 C705: library part CAP_POLAR, "Polar Capacitor"
HDR500 HDR600 HDR601 HDR602 HDR603 HDR604 HDR605 HDR606 HDR607: "Header, 2-Pin"
HDR501: "Header, 5-Pin, Dual row"
J600: "Low Voltage Power Supply Sonnector"
J700: library part "D Connector 9", "Receptacle Assembly, 9 Position, Right Angle"
JP400_PortIOA JP400_PortIOB JP400_PortIOC JP400_PortIOD: "Header, 30-Pin, Dual row"
R200 R401_PortIOA R401_PortIOB R401_PortIOC R401_PortIOD R402_PortIOA R402_PortIOB R402_PortIOC R402_PortIOD R403_PortIOA R403_PortIOB R403_PortIOC R403_PortIOD R500 R600 R601 R602 R603 R604 R605 R606 R700: library part Res2, "Resistor"
RA400_PortIOA RA400_PortIOB RA400_PortIOC RA400_PortIOD RA401_PortIOA RA401_PortIOB RA401_PortIOC RA401_PortIOD RA402_PortIOA RA402_PortIOB RA402_PortIOC RA402_PortIOD RA403_PortIOA RA403_PortIOB RA403_PortIOC RA403_PortIOD RA404_PortIOA RA404_PortIOB RA404_PortIOC RA404_PortIOD RA405_PortIOA RA405_PortIOB RA405_PortIOC RA405_PortIOD RA406_PortIOA RA406_PortIOB RA406_PortIOC RA406_PortIOD RA407_PortIOA RA407_PortIOB RA407_PortIOC RA407_PortIOD RA408_PortIOA RA408_PortIOB RA408_PortIOC RA408_PortIOD RA409_PortIOA RA409_PortIOB RA409_PortIOC RA409_PortIOD RA410_PortIOA RA410_PortIOB RA410_PortIOC RA410_PortIOD RA411_PortIOA RA411_PortIOB RA411_PortIOC RA411_PortIOD RA500 RA501 RA502 RA503 RA504 RA505: library part MNR34, "3216x4 Resistor Array"
S600: library part PCB_MOUNT_SWITCH, "SPDT Subminiature Toggle Switch"
SW200: "SPNA SMD Keyboard Switch"
U1: "Spartan-IIE 1.8V FPGA, 208-Pin PQFP, Standard Performance, Commercial Grade"
U200: library part XO_CAN_DIP14_1M, "IC, Oscillator, Canned, CMOS o/p, General Purpose, No Enable/Disable, 32MHz"
U201: "Hex Inverter with 5V-Tolerant Inputs"
U500: "Low-Voltage Quad 2-Input Multiplexer with 5V-Tolerant Inputs (Non-Inverting)"
U501: "XCF00S Series, Platform Flash In-System Programmable Configuration 3.3V PROM, 20-Pin TSOP, 4-Megabit, Commercial Grade"
U600 U601: "5A Low Dropout Possitive Regulators"
U700: "3.0V TO 5.5V, Low-Power, up to 1Mbps, True RS-232 Transceiver Using Four 0.1µF External Capacitor"

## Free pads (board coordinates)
  round 39.37 hole 19.68: 0(-90.05,-1107.42) GND(-1423.77,-1716.41) GND(-1423.77,-1416.41) GND(-1423.77,-1116.41) GND(-1423.77,-816.41) GND(-1355.26,1425.8) GND(-1055.26,1425.8) GND(-755.26,1425.8) GND(-455.26,1425.8) GND(324.74,-1784.91) GND(624.74,-1784.91) GND(924.74,-1784.91) GND(1224.74,-1784.91) GND(1388.24,23.59) GND(1388.24,323.59) GND(1388.24,623.59) GND(1388.24,923.59)
  round 39.37 smd paste-19.68 mask+39.37: FID(-601.88,-569.32) FID(571.35,603.9) FID(2169.93,-2228.77)

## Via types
v1: diameter 40, hole 19.68, Top Layer to Bottom Layer, 173 vias

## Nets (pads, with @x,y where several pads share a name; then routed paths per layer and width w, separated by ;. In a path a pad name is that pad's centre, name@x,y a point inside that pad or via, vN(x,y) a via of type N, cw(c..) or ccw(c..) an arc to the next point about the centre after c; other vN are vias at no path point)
5V: C232.1 C600.1 C602.1 C605.1 JP400_PortIOA.27 JP400_PortIOA.29 JP400_PortIOA.31 JP400_PortIOA.33 JP400_PortIOB.27 JP400_PortIOB.29 JP400_PortIOB.31 JP400_PortIOB.33 JP400_PortIOC.27 JP400_PortIOC.29 JP400_PortIOC.31 JP400_PortIOC.33 JP400_PortIOD.27 JP400_PortIOD.29 JP400_PortIOD.31 JP400_PortIOD.33 S600.3 U200.14 U600.3 U601.3 | length 21272.8
  Top Layer w12: -257.4,-2255.73 C232.1@-257.4,-2185 -257.4,-2255.73 ; -257.4,-2255.73 -214.03,-2299.1 ; -257.4,-2255.73 -214.03,-2299.1 ; -214.03,-2396.14 -214.03,-2299.1 ; -214.03,-2396.14 JP400_PortIOB.31@-165.26,-2444.91 -214.03,-2396.14 ; -214.03,-2396.14 -214.03,-2299.1
  Top Layer w24: v1@1644.74,2795.12 v1(1644.74,2791.19) C600.1@1644.74,2171.35 ; C232.1@-280,-2162.4 C232.1@-257.4,-2185 C232.1@-280,-2162.4 ; C232.1@-280,-2162.4 U200.14@-280,-2020 C232.1@-280,-2162.4 ; C600.1@1644.74,2171.35 1822.77,2171.35 ; C600.1@1644.74,2171.35 1822.77,2171.35 ; 1822.77,2171.35 1864.74,2129.38 ; 1822.77,2171.35 1864.74,2129.38 ; 1864.74,2129.38 U601.3@1864.74,2032.29 1864.74,2129.38 ; 2344.74,2141.13 C602.1@2436.84,2233.24 ; 2344.74,2141.13 U600.3@2344.74,2032.29 2344.74,2141.13 ; 2344.74,2141.13 v1(2362.2,2159.45) C602.1@2436.84,2233.24 ; C602.1@2436.84,2233.24 C602.1@2444.74,2233.24 C602.1@2436.84,2233.24
  Bottom Layer w24: -2301.18,-526.41 JP400_PortIOA.27@-2083.77,-526.41 ; -2301.18,-426.41 JP400_PortIOA.29@-2083.77,-426.41 ; -2301.18,-326.41 JP400_PortIOA.31@-2083.77,-326.41 ; -2301.18,-226.41 JP400_PortIOA.33@-2083.77,-226.41 ; -265.26,-2687.99 JP400_PortIOB.33@-265.26,-2444.91 ; JP400_PortIOD.27@-165.66,2087.37 -165.66,2325.32 ; -165.26,-2687.99 JP400_PortIOB.31@-165.26,-2444.91 ; JP400_PortIOD.29@-65.66,2087.37 -65.66,2325.32 ; -65.26,-2687.99 JP400_PortIOB.29@-65.26,-2444.91 ; JP400_PortIOD.31@34.34,2087.37 34.34,2325.32 ; 34.74,-2687.99 JP400_PortIOB.27@34.74,-2444.91 ; JP400_PortIOD.33@134.34,2087.37 134.34,2325.32 ; JP400_PortIOC.33@2053.24,-526.41 2362.2,-526.41 ; JP400_PortIOC.31@2053.24,-426.41 2362.2,-426.41 ; JP400_PortIOC.29@2053.24,-326.41 2362.2,-326.41 ; JP400_PortIOC.27@2053.24,-226.41 2362.2,-226.41
  Bottom Layer w50: 2306.37,2570.66 2408.16,2672.29 S600.3@2484.74,2672.29
  Bottom Layer w100: -2301.18,-226.38 -2301.18,-326.41 -2301.18,-426.41 -2301.18,-526.41 -2301.18,-1977.36 -1589.57,-2687.99 -265.26,-2687.99 -165.26,-2687.99 -65.26,-2687.99 34.74,-2687.99 1583.66,-2687.99 2362.2,-1910.43 2362.2,-526.41 2362.2,-426.41 2362.2,-326.41 2362.2,-226.38 v1(2362.2,2159.45) 2362.2,2514.76 2306.37,2570.66 C605.1@2184.74,2692.29 C605.1@2185.03,2692 ; -165.66,2325.32 -65.66,2325.32 34.34,2325.32 134.34,2325.32 369.05,2325.32 834.72,2791 834.91,2791.19 v1(1644.74,2791.19) 1993.08,2791.19 1993.27,2791 2091.98,2692.29 C605.1@2184.74,2692.29
  other v1: 2362.2,2159.45
CCLK: U1.155 U501.3 | length 3815.4
  Top Layer w6: v1(-897.91,-627.23) -916.61,-608.53 -916.61,-491.44 -867.11,-441.94 -672,-441.94 -648.95,-464.99 U1.155@-601.88,-464.99
  Top Layer w10: U501.3@-2311.29,1821.54 -2311.29,1866.86 -2295.19,1882.96 -2004.91,1882.96 -1922.48,1800.53 v1(-1922.48,1559.45)
  Bottom Layer w8: v1(-1922.48,1559.45) -1463.71,1100.68 -1463.71,-61.43 v1(-897.91,-627.23)
CFG_DIN: U1.153 U501.1 | length 3712.4
  Top Layer w6: v1(-978.6,-651.83) -978.6,-508.25 -888.29,-417.94 -662.06,-417.94 -654.38,-425.62 U1.153@-601.88,-425.62
  Top Layer w10: U501.1@-2260.11,1821.54 -2216.41,1865.24 -2114.14,1865.24 -2074.78,1825.88 -2074.78,1659.58 v1(-1847.48,1432.28)
  Bottom Layer w8: v1(-1847.48,1432.28) -1847.48,1382.11 -1813.7,1348.32 -1525.7,1060.33 -1525.7,-104.72 v1(-978.6,-651.83)
CFG_INIT: RA500.2 U1.107 U501.8 | length 2699.3
  Top Layer w6: -938.26,477.8 -924.97,464.52 -667.03,464.52 -651.66,479.89 U1.107@-601.88,479.89
  Top Layer w10: U501.8@-2439.24,1821.54 -2439.24,1714.09 -2411.3,1686.16 -2235.17,1686.16 -2208.6,1712.72 -2208.6,1762.91 -2194.22,1777.29 -2134.42,1777.29 -2114.14,1757 -2114.14,1628.1 -1962.6,1476.56 -1962.6,1390.96 -1847.47,1275.83 -1736.28,1275.83 -1712.59,1252.14 -938.26,477.8
CLK_BRD: U1.182 U201.2 | length 498.2
  Top Layer w6: U1.182@-25.11,-569.32 -25.11,-606.52 -64.42,-645.83 -64.42,-889.26 6,-959.68 U201.2@6,-1022.08
CTS: J700.7 U700.9 | length 754.9
  Top Layer w10: U700.9@2280.17,-2228.77 2280.17,-2321.44 2300.09,-2341.36 2429.98,-2341.36 2531.33,-2442.71 2531.33,-2666.08 2507.71,-2689.69 2474.17,-2689.69 J700.7@2424.26,-2739.6
DONE: R500.2 U1.104 U501.10 | length 2663.4
  Top Layer w6: -667.45,650.77 -524.73,650.77 -517.23,643.28 U1.104@-517.23,603.91
  Top Layer w8: -869.38,832.04 -688.1,650.77 -667.47,650.77
  Top Layer w10: R500.2@-2597.86,1732.29 -2497.78,1732.29 ; U501.10@-2490.42,1821.54 -2490.42,1768.81 -2497.78,1761.45 -2497.78,1732.29 ; v1(-2023.61,1463.77) -2188.92,1629.08 -2226.31,1666.48 -2431.97,1666.48 -2497.78,1732.29 ; v1(-1903.56,1423.43) -1812.05,1331.92 -1424.35,1331.92 -924.48,832.04 -869.38,832.04
  Bottom Layer w8: v1(-2023.61,1463.77) -1943.9,1463.77 v1(-1903.56,1423.43)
